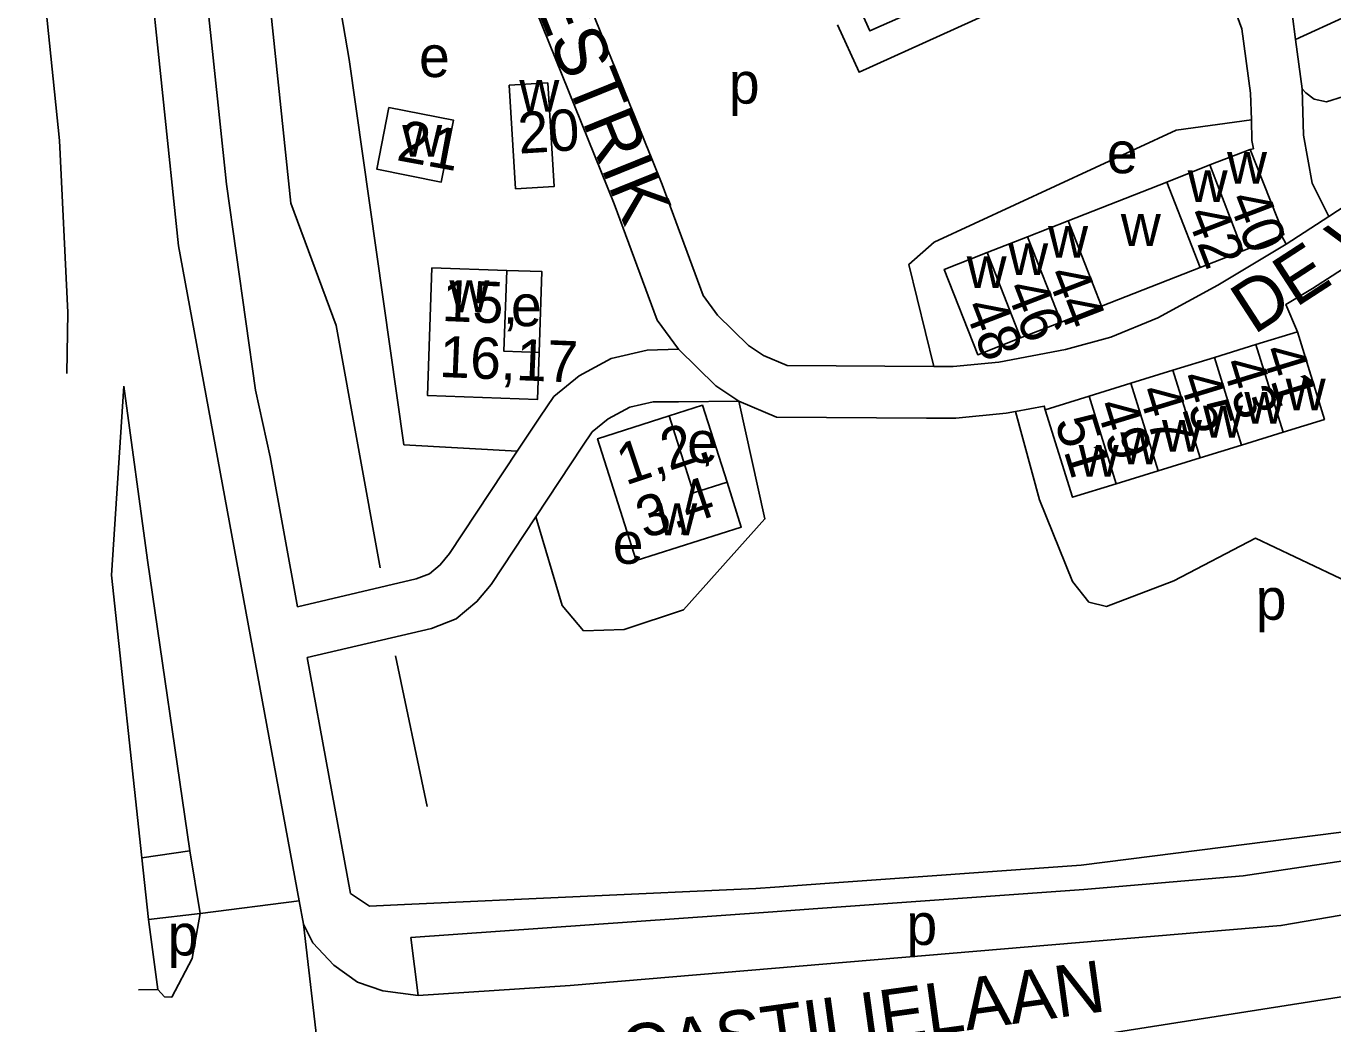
# Model space of a CAD drawing. Extents: x 159441 to 162086, y 388175 to 389787.
# Drawn here: x 159462.7 to 159589.2, y 389104.6 to 389201.2 of the extents above; entities that cross this region are included whole.
import ezdxf

# ---------------------------------------------------------------- set-up
doc = ezdxf.new("R2010")
doc.units = 0
for name, color, linetype in [('BLT_Basislijn', 7, 'Continuous'), ('BLT_Bebouwing', 7, 'Continuous'), ('BLT_Centroide', 7, 'Continuous'), ('BLT_Huisnummer', 7, 'Continuous'), ('BLT_Huisnummer_ tussenligend', 7, 'Continuous'), ('BLT_Huisnummer_reeks', 7, 'Continuous'), ('BLT_Onderverdeling_panden', 7, 'Continuous'), ('BLT_Straatnaam', 7, 'Continuous'), ('BLT_Vlakafsluiter', 7, 'Continuous')]:
    doc.layers.add(name, color=color, linetype=linetype)

msp = doc.modelspace()

# ---------------------------------------------------------------- linework, layer by layer
at = {"layer": 'BLT_Basislijn'}
for p, q in [((159588.81, 389182.75), (159621.55, 389204.49)), ((159585.57, 389199.9), (159586.21, 389195.1)), ((159584.66, 389180.08), (159588.81, 389182.75)), ((159584.23, 389180.91), (159584.66, 389180.08)), ((159477.47, 389179.91), (159489.15, 389116.52)), ((159587.23, 389175.79), (159591.58, 389178.59)), ((159525.85, 389164.83), (159531.7, 389164.89)), ((159486.32, 389159.49), (159488.99, 389144.99)), ((159501.54, 389125.64), (159498.47, 389140.23)), ((159564.84, 389119.96), (159594.28, 389123.71)), ((159478.56, 389121.36), (159473.9, 389120.68)), ((159473.9, 389120.68), (159474.55, 389114.72)), ((159478.56, 389121.36), (159479.54, 389115.29)), ((159540.03, 389118.19), (159564.84, 389119.96)), ((159535.18, 389117.84), (159540.03, 389118.19)), ((159499.33, 389116.16), (159533.35, 389117.71)), ((159533.35, 389117.71), (159535.18, 389117.84)), ((159489.15, 389116.52), (159489.56, 389114.25)), ((159539.33, 389115.77), (159534.52, 389115.43)), ((159479.54, 389115.29), (159474.55, 389114.72)), ((159474.55, 389114.72), (159475.44, 389107.92)), ((159534.52, 389115.43), (159499.95, 389112.98)), ((159499.95, 389112.98), (159500.66, 389107.35))]:
    msp.add_line(p, q, dxfattribs=at)
for points in [[(159506.19, 389232.2), (159496.79, 389252.48), (159489.43, 389249.06), (159490.03, 389220.95), (159493.99, 389197.94), (159499.28, 389160.67), (159510.25, 389160.05)], [(159496.98, 389148.76), (159492.71, 389172.21), (159488.32, 389184.06), (159481.73, 389247.36)], [(159517.77, 389233.21), (159510.22, 389229.24), (159509.12, 389227.73), (159508.63, 389226.04), (159508.77, 389224.18), (159524.26, 389185.85)], [(159504.56, 389229.96), (159503.58, 389226.56), (159503.84, 389223.04), (159519.62, 389183.98)], [(159477.76, 389227.17), (159482.11, 389185.89), (159484.92, 389165.95), (159486.32, 389159.49)], [(159477.47, 389179.91), (159472.91, 389223.51)], [(159466.65, 389167.57), (159466.74, 389173.45), (159465.93, 389190.1), (159462.71, 389221.52)], [(159580.58, 389214.9), (159585.27, 389202.13), (159585.57, 389199.9)], [(159541.25, 389201.3), (159543.33, 389196.72), (159576.42, 389211.72)], [(159576.42, 389211.72), (159580.39, 389200.92), (159581.22, 389194.7), (159581.3, 389192.1)], [(159585.57, 389199.9), (159595.44, 389204.45), (159599.83, 389206.95), (159607.37, 389206.71), (159609.15, 389206.37), (159610.42, 389205.52), (159611.34, 389204.36), (159611.8, 389203.5), (159612.41, 389200.35), (159606.67, 389197.56), (159604.75, 389200.33), (159590.21, 389194.36), (159588.59, 389193.85), (159587.38, 389194.12), (159586.57, 389194.72), (159586.21, 389195.1)], [(159614.83, 389194.03), (159634.55, 389161.07), (159635.99, 389156.12), (159635.67, 389152.38), (159634.44, 389149.9), (159630.01, 389147.42), (159614.32, 389141.73), (159607.23, 389141.83), (159595.03, 389145.29), (159581.7, 389151.61), (159573.81, 389147.49), (159567.28, 389145.02), (159565.58, 389145.44), (159563.98, 389147.44), (159560.8, 389155.34), (159558.48, 389163.88)], [(159586.21, 389195.1), (159586.34, 389190.64), (159587.2, 389185.98), (159588.81, 389182.75)], [(159581.3, 389192.1), (159574.04, 389191.1), (159550.59, 389180.27), (159548.16, 389178.11), (159550.58, 389168.24)], [(159581.3, 389192.1), (159581.35, 389190.11), (159581.5, 389189.31), (159581.2, 389189.25)], [(159550.58, 389168.24), (159536.38, 389168.32), (159534.09, 389169.3), (159532.64, 389170.28), (159529.64, 389173.19), (159528.24, 389175.11), (159524.26, 389185.85)], [(159519.62, 389183.98), (159523.79, 389172.73), (159525.85, 389169.9)], [(159584.66, 389180.08), (159578.05, 389176.12), (159572.26, 389172.96), (159567.69, 389171.06), (159563.31, 389169.88), (159556.86, 389168.66), (159552.45, 389168.23), (159550.58, 389168.24)], [(159509.24, 389177.53), (159512.63, 389177.42), (159512.37, 389169.59)], [(159585.77, 389171.6), (159584.65, 389174.24), (159587.23, 389175.79)], [(159510.25, 389160.05), (159512.42, 389163.33), (159513.8, 389165.32), (159516.25, 389167.34), (159519.33, 389169.01), (159522.83, 389169.83), (159525.85, 389169.9)], [(159525.85, 389169.9), (159529.48, 389166.38), (159531.7, 389164.89)], [(159472.16, 389166.33), (159470.98, 389148.03), (159473.9, 389120.68)], [(159472.16, 389166.33), (159474.46, 389149.48), (159478.56, 389121.36)], [(159512.05, 389153.69), (159514.6, 389145.1), (159516.67, 389142.64), (159520.6, 389142.78), (159526.34, 389144.67), (159534.22, 389153.49), (159531.7, 389164.89)], [(159531.7, 389164.89), (159535.34, 389163.33), (159549.85, 389163.24)], [(159512.05, 389153.69), (159516.56, 389160.52), (159517.51, 389161.9), (159519.06, 389163.18), (159521.13, 389164.3), (159523.41, 389164.83), (159525.85, 389164.83)], [(159524.94, 389163.45), (159528.17, 389164.48), (159530.55, 389157.03)], [(159549.85, 389163.24), (159552.69, 389163.23), (159557.56, 389163.71), (159558.48, 389163.88)], [(159558.48, 389163.88), (159561.25, 389164.4), (159561.36, 389164.05)], [(159488.99, 389144.99), (159500.47, 389147.67), (159501.76, 389148.17), (159502.79, 389149.03), (159503.7, 389150.12), (159510.25, 389160.05)], [(159489.9, 389140.06), (159501.95, 389142.88), (159504.34, 389143.8), (159506.34, 389145.48), (159507.72, 389147.13), (159512.05, 389153.69)], [(159673.65, 389140.54), (159670.9, 389144.58), (159670.52, 389144.52), (159664.4, 389141.49), (159650.05, 389135.35), (159631.04, 389128.66), (159612.1, 389124.04), (159597.36, 389121.44), (159580.52, 389118.94), (159565.08, 389117.6), (159539.33, 389115.77)], [(159489.9, 389140.06), (159494.1, 389117.24), (159495.95, 389116.01), (159499.33, 389116.16)], [(159500.66, 389107.35), (159515.37, 389108.32), (159584.16, 389114.12), (159614.49, 389119.32), (159626.1, 389122.22), (159641.74, 389127.26), (159662.12, 389135.14), (159673.65, 389140.54)], [(159525.86, 389097.11), (159551.4, 389101.15), (159604.37, 389109.5), (159624.03, 389113.78), (159632.93, 389116.43), (159648.23, 389121.53), (159666.92, 389129.4), (159672.01, 389132.06)], [(159476.82, 389107.19), (159478.79, 389110.92), (159479.54, 389115.29)], [(159489.56, 389114.25), (159490.45, 389112.45), (159492.49, 389110.29), (159494.79, 389108.64), (159497.24, 389107.8), (159500.66, 389107.35)], [(159475.44, 389107.92), (159476.11, 389107.23), (159476.82, 389107.19)]]:
    msp.add_lwpolyline(points, dxfattribs=at)
at = {"layer": 'BLT_Bebouwing'}
for p, q in [((159581.2, 389189.25), (159577.27, 389187.75)), ((159577.27, 389187.75), (159573.12, 389186.08)), ((159573.12, 389186.08), (159563.56, 389182.33)), ((159563.56, 389182.33), (159559.64, 389180.79)), ((159559.64, 389180.79), (159555.73, 389179.26)), ((159580.49, 389179.44), (159584.23, 389180.91)), ((159580.49, 389179.44), (159576.36, 389177.82)), ((159566.8, 389174.07), (159576.36, 389177.82)), ((159566.8, 389174.07), (159562.88, 389172.54)), ((159558.97, 389171), (159562.88, 389172.54)), ((159581.74, 389170.36), (159585.77, 389171.6)), ((159577.72, 389169.11), (159581.74, 389170.36)), ((159573.71, 389167.87), (159577.72, 389169.11)), ((159569.65, 389166.62), (159573.71, 389167.87)), ((159565.6, 389165.36), (159569.65, 389166.62)), ((159561.36, 389164.05), (159565.6, 389165.36)), ((159584.37, 389161.88), (159580.34, 389160.63)), ((159576.34, 389159.4), (159580.34, 389160.63)), ((159576.34, 389159.4), (159572.27, 389158.14)), ((159568.22, 389156.89), (159572.27, 389158.14))]:
    msp.add_line(p, q, dxfattribs=at)
for points in [[(159545.71, 389205.74), (159542.73, 389204.39), (159544.38, 389200.71), (159554.47, 389205.2)], [(159584.23, 389180.91), (159584.46, 389181), (159581.2, 389189.25)], [(159555.73, 389179.26), (159551.58, 389177.63), (159554.82, 389169.37), (159558.97, 389171)], [(159509.24, 389177.53), (159501.99, 389177.77), (159501.56, 389165.42), (159512.21, 389165.05), (159512.37, 389169.59)], [(159512.37, 389169.59), (159508.96, 389169.71), (159509.24, 389177.53)], [(159585.77, 389171.6), (159588.38, 389163.12), (159584.37, 389161.88)], [(159568.22, 389156.89), (159563.98, 389155.58), (159561.36, 389164.05)], [(159524.94, 389163.45), (159518.02, 389161.25), (159521.76, 389149.46), (159531.92, 389152.7), (159530.55, 389157.03)], [(159530.55, 389157.03), (159527.31, 389156), (159524.94, 389163.45)]]:
    msp.add_lwpolyline(points, dxfattribs=at)
for points in [[(159509.47, 389195.46), (159513.2, 389195.69), (159513.83, 389185.66), (159510.09, 389185.44)], [(159497.83, 389193.31), (159496.66, 389187.32), (159502.89, 389186.09), (159504.06, 389192.09)]]:
    msp.add_lwpolyline(points, close=True, dxfattribs=at)
at = {"layer": 'BLT_Onderverdeling_panden'}
for p, q in [((159577.27, 389187.75), (159580.49, 389179.44)), ((159576.36, 389177.82), (159573.12, 389186.08)), ((159563.56, 389182.33), (159566.8, 389174.07)), ((159562.88, 389172.54), (159559.64, 389180.79)), ((159555.73, 389179.26), (159558.97, 389171)), ((159581.74, 389170.36), (159584.37, 389161.88)), ((159580.34, 389160.63), (159577.72, 389169.11)), ((159573.71, 389167.87), (159576.34, 389159.4)), ((159572.27, 389158.14), (159569.65, 389166.62)), ((159565.6, 389165.36), (159568.22, 389156.89))]:
    msp.add_line(p, q, dxfattribs=at)
at = {"layer": 'BLT_Vlakafsluiter'}
for p, q in [((159479.54, 389115.29), (159489.15, 389116.52)), ((159491.51, 389097.27), (159489.56, 389114.25)), ((159475.44, 389107.92), (159473.58, 389107.9))]:
    msp.add_line(p, q, dxfattribs=at)

# ---------------------------------------------------------------- texts
at = {"layer": 'BLT_Centroide'}
for s, p in [('e', (159500.74, 389196.25)), ('p', (159530.73, 389193.68)), ('w', (159510.45, 389192.89)), ('w', (159499.11, 389188.54)), ('e', (159567.32, 389186.94)), ('w', (159578.95, 389185.93)), ('w', (159575.14, 389184.15)), ('w', (159568.67, 389179.91)), ('w', (159561.63, 389178.76)), ('w', (159557.77, 389177.09)), ('w', (159553.75, 389175.84)), ('w', (159503.68, 389173.49)), ('e', (159509.64, 389172.14)), ('w', (159584.63, 389163.99)), ('w', (159580.63, 389162.69)), ('w', (159576.63, 389161.36)), ('w', (159572.65, 389159.99)), ('e', (159526.69, 389158.92)), ('w', (159568.62, 389158.78)), ('w', (159564.59, 389157.56)), ('w', (159523.79, 389151.91)), ('e', (159519.49, 389149.14)), ('p', (159581.73, 389143.72)), ('p', (159476.41, 389111.23)), ('p', (159547.92, 389112.25))]:
    msp.add_text(s, height=4, dxfattribs=at).set_placement(p)
at = {"layer": 'BLT_Huisnummer'}
for s, rotation, p in [('20', 3.6171, (159510.43, 389188.83)), ('21', 349.6171, (159498.46, 389188.22)), ('40', 291.0028, (159578.97, 389184.44)), ('44', 291.0028, (159561.42, 389177.17)), ('48', 291.0028, (159553.41, 389174.03)), ('41', 287.0028, (159582.26, 389169.78)), ('45', 287.0028, (159574.25, 389167.19)), ('51', 287.0028, (159562.25, 389162.92))]:
    msp.add_text(s, height=4, rotation=rotation, dxfattribs=at).set_placement(p)
at = {"layer": 'BLT_Huisnummer_ tussenligend'}
for s, rotation, p in [('42', 291.0028, (159574.94, 389182.97)), ('46', 291.0028, (159557.45, 389175.83)), ('43', 287.0028, (159578.42, 389168.55)), ('47', 287.0028, (159570.31, 389165.88)), ('49', 287.0028, (159566.21, 389164.51))]:
    msp.add_text(s, height=4, rotation=rotation, dxfattribs=at).set_placement(p)
at = {"layer": 'BLT_Huisnummer_reeks'}
for s, rotation, p in [('15,', 357.6171, (159502.89, 389172.65)), ('16,17', 357.6171, (159502.65, 389167.23)), ('1,2,', 18.6171, (159520.73, 389156.7)), ('3,4', 18.6171, (159522.59, 389151.52))]:
    msp.add_text(s, height=4, rotation=rotation, dxfattribs=at).set_placement(p)
at = {"layer": 'BLT_Straatnaam'}
for s, rotation, p in [('WESTRIK', 292.0004, (159509.27, 389209.88)), ('DE VOORSTAD', 33.0004, (159581.54, 389171.26)), ('CASTILIELAAN', 7.9013, (159520.61, 389099.37))]:
    msp.add_text(s, height=5, rotation=rotation, dxfattribs=at).set_placement(p)

doc.saveas('drawing.dxf')
